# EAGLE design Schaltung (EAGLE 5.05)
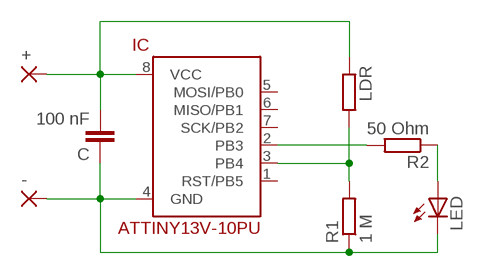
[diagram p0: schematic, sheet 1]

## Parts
+  2,15/1,0  [2,15/1,0]
-  2,15/1,0  [2,15/1,0]
C  100 nF  C7.5/3  [C7.5B3]
IC  ATTINY13V-10PU  [DIL08]
LDR  R-EU_0207/7  [0207/7]
LED  LED5MM  [LED5MM]
R1  1 M  R-EU_0207/7  [0207/7]
R2  50 Ohm  R-EU_0207/7  [0207/7]

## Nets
GND: -.1(P) C.1 IC.4(GND) LED.K(C) R1.1
N$1: +.1(P) C.2 IC.8(VCC) LDR.1
N$3: LED.A R2.1
N$4: IC.2(PB3) R2.2
N$5: IC.3(PB4) LDR.2 R1.2
Unconnected: IC.1(RST/PB5) IC.5(MOSI/PB0) IC.6(MISO/PB1) IC.7(SCK/PB2)

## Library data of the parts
+ - = wirepad:2,15/1,0: THROUGH-HOLE PAD
C = capacitor-wima:C: CAPACITOR
IC = attiny13:ATTINY13V-10*
LDR R1 R2 = resistor:R-EU_: RESISTOR, European symbol
LED = led:LED: LED

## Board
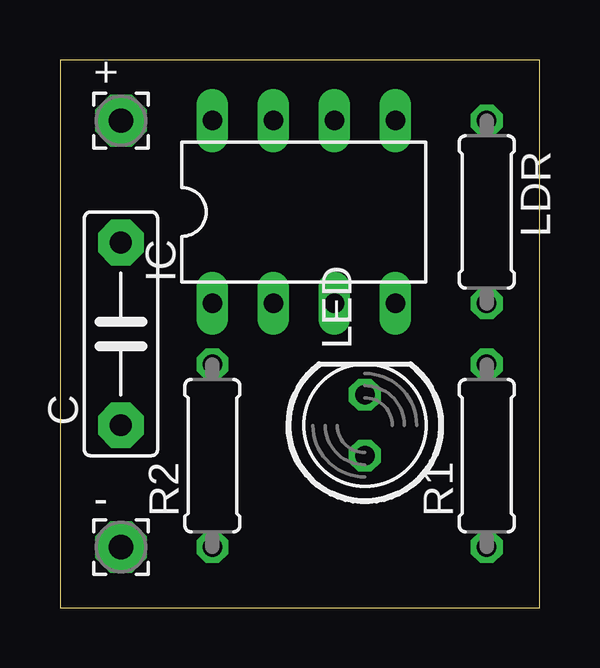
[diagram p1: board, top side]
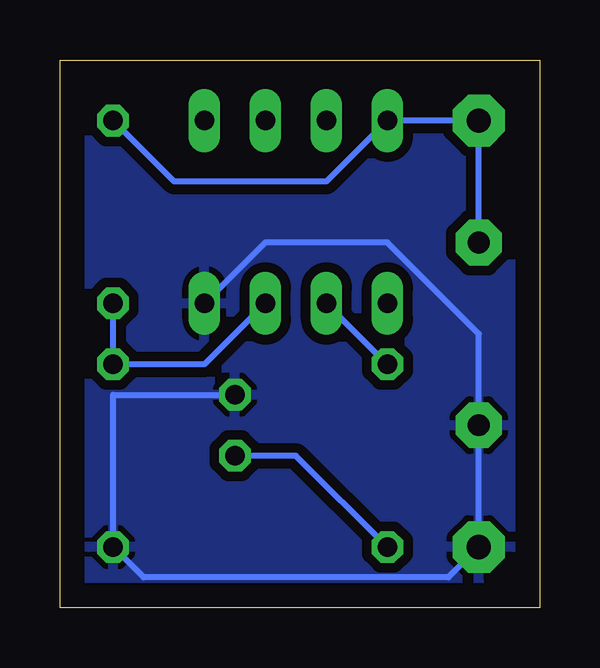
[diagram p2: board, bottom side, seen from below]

Size 19.99 x 22.85 mm. Coordinates in mm from the lower left corner, seen from the top.
Outline: 0,0 19.99,0 19.99,22.85 0,22.85 0,0
Copper layers (1*16): Top 0.035mm / dielectric 1.5mm / Bottom 0.035mm
Design rules "default *": minimum track width 10mil, minimum drill 24mil, track to track 16mil, track to pad 16mil, pad to pad 16mil, via to via 16mil, smd to smd 8mil, copper to edge 40mil, drill to drill 8mil, minimum pad ring 10mil, minimum via ring 8mil, stop-mask expansion 4mil, vias tented up to drill 0mil, thermal gap 10mil

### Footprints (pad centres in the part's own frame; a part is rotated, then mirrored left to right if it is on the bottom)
2,15/1,0 = drill 1.016 pad 2.159 octagon: 1 0,0
C7.5B3 = drill 0.914 pad 1.905 octagon: 1 -3.81,0; 2 3.81,0
DIL08 = drill 0.813 long: 1 -3.81,-3.81; 2 -1.27,-3.81; 3 1.27,-3.81; 4 3.81,-3.81; 5 3.81,3.81; 6 1.27,3.81; 7 -1.27,3.81; 8 -3.81,3.81
0207/7 = drill 0.813 octagon: 1 -3.81,0; 2 3.81,0
LED5MM = drill 0.813 octagon: A -1.27,0; K 1.27,0

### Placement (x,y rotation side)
+  2.54,20.32 0 top
-  2.54,2.54 0 top
C  2.54,11.43 90 top
IC  10.16,16.51 0 top
LDR  17.78,16.51 270 top
LED  12.7,7.62 90 top
R1  17.78,6.35 90 top
R2  6.35,6.35 90 top

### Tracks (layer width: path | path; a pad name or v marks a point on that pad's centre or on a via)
GND
  Bottom 0.254: LED.K 17.78,8.89 R1.1 16.51,1.27 3.81,1.27 -.1 C.1 2.54,11.43 6.35,15.24 11.43,15.24 IC.4
  pour Bottom: -3.81,26.67 22.86,26.67 22.86,-2.54 -3.81,-2.54
N$1
  Bottom 0.254: LDR.1 15.24,17.78 8.89,17.78 IC.8 +.1 C.2
N$3
  Bottom 0.254: R2.1 10.16,6.35 LED.A
N$4
  Bottom 0.254: R2.2 IC.2
N$5
  Bottom 0.254: LDR.2 R1.2 13.97,10.16 IC.3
